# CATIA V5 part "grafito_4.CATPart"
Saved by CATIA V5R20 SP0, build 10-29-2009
Part number: grafito_4
Revision: ANY
Definition: UNKNOWN
Nomenclature: grafito
Source: Unknown
Bounding box of the stored display mesh (mm): x -2.45 to 2.486, y 2.846 to 22.843, z -2.5 to 2.5
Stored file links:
  C:\Users\Utente\Desktop\IO LAVORO\3D X SITO CF\CUMSA\3D files SD\SD 4528\grafito_4.CATPart
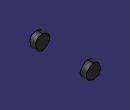
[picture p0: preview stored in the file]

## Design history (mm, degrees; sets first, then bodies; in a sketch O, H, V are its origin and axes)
Body1 "Saliente-Extruir1" (main body)
  Solid1: solid without history
Body2 "Saliente-Extruir1"
  Solid2: solid without history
